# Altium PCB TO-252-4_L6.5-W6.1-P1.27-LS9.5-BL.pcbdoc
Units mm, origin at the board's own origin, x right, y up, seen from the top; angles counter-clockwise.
Board outline 19.35 x 23.63 mm, 2 copper layers (Top Layer, Bottom Layer), stack 0 mm thick; 1 components, 0 nets, 5 pads, 0 vias.
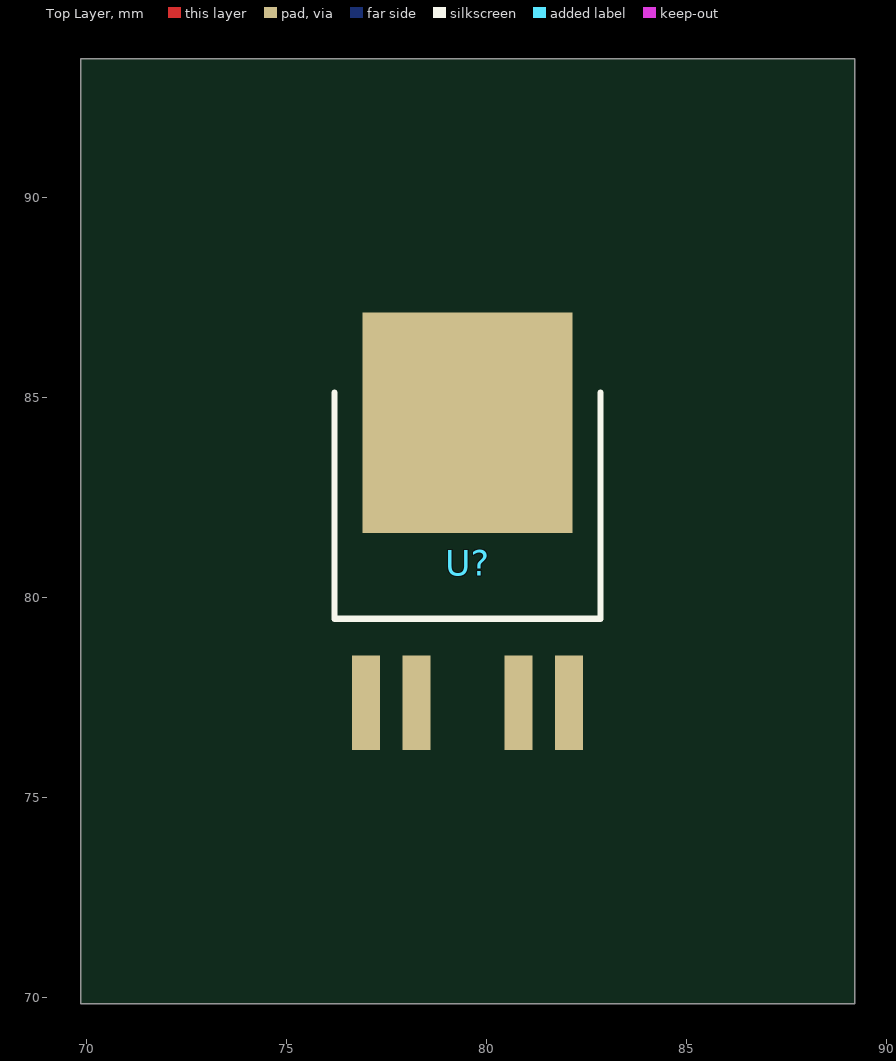
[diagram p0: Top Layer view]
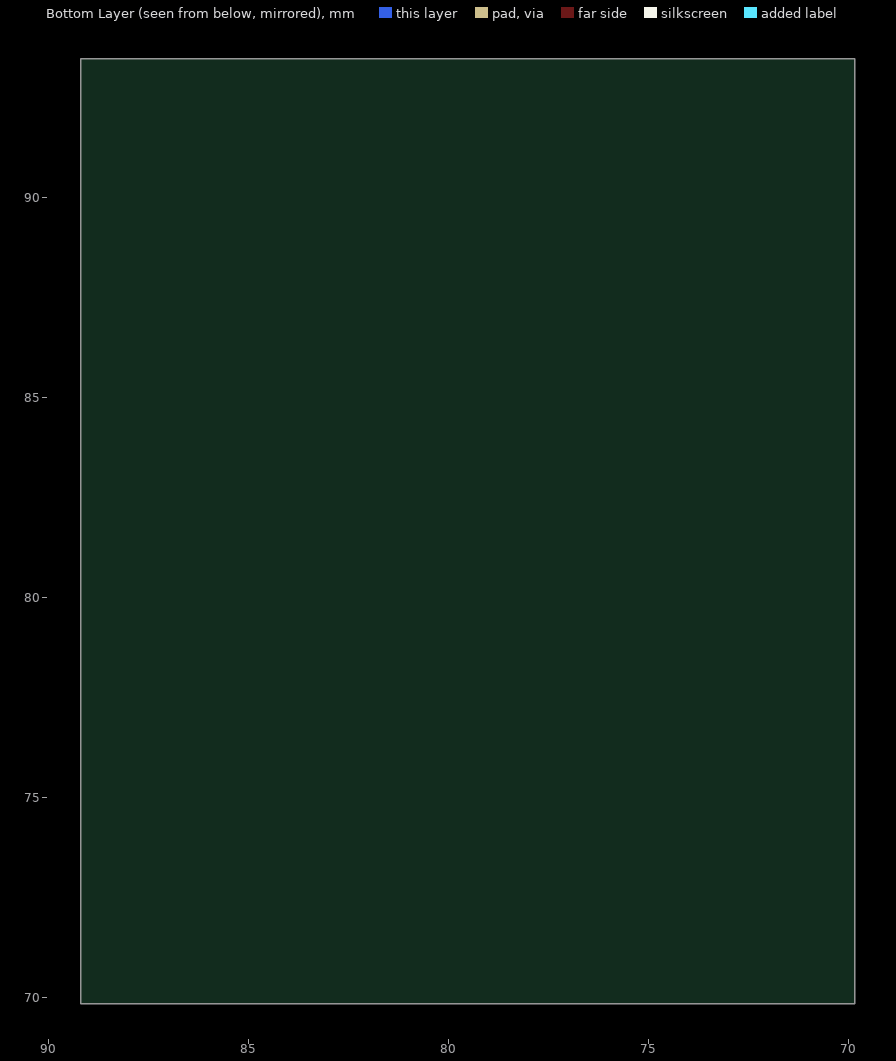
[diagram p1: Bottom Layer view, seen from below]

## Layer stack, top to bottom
Top Layer: signal copper (thickness not stored)
Bottom Layer: signal copper (thickness not stored)

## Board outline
89.202,69.85 69.85,69.85 69.85,93.484 89.202,93.484

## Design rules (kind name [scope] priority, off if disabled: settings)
PasteMaskExpansion "Paste Mask Expansion" [All] p1: expansion=0
SolderMaskExpansion "Solder Mask Expansion" [IsVia] p1: expansion=-25.4 istentingtop=TRUE
SolderMaskExpansion "Solder Mask Expansion" [All] p2: expansion=0.051 istentingtop=FALSE

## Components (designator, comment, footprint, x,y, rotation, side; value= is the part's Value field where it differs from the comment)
U? "" TO-252-4_L6.5-W6.1-P1.27-LS9.5-BL 79.526,80.878 r0 top

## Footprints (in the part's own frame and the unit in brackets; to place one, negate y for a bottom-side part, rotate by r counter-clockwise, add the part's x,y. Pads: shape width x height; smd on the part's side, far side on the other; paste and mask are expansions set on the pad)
TO-252-4_L6.5-W6.1-P1.27-LS9.5-BL [mm]
  rect 0.7x2.357 smd: 1(-2.54,-3.5) 2(-1.27,-3.5) 4(1.27,-3.5) 5(2.54,-3.5)
  rect 5.249x5.512 smd: 3(0,3.5)
  silkscreen extent -3.33,-1.4 3.33,4.25

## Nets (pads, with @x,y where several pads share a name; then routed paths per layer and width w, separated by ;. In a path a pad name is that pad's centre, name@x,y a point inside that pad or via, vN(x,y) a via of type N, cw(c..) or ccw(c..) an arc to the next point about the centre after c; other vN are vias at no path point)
pads on no net: U?.1 U?.2 U?.3 U?.4 U?.5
